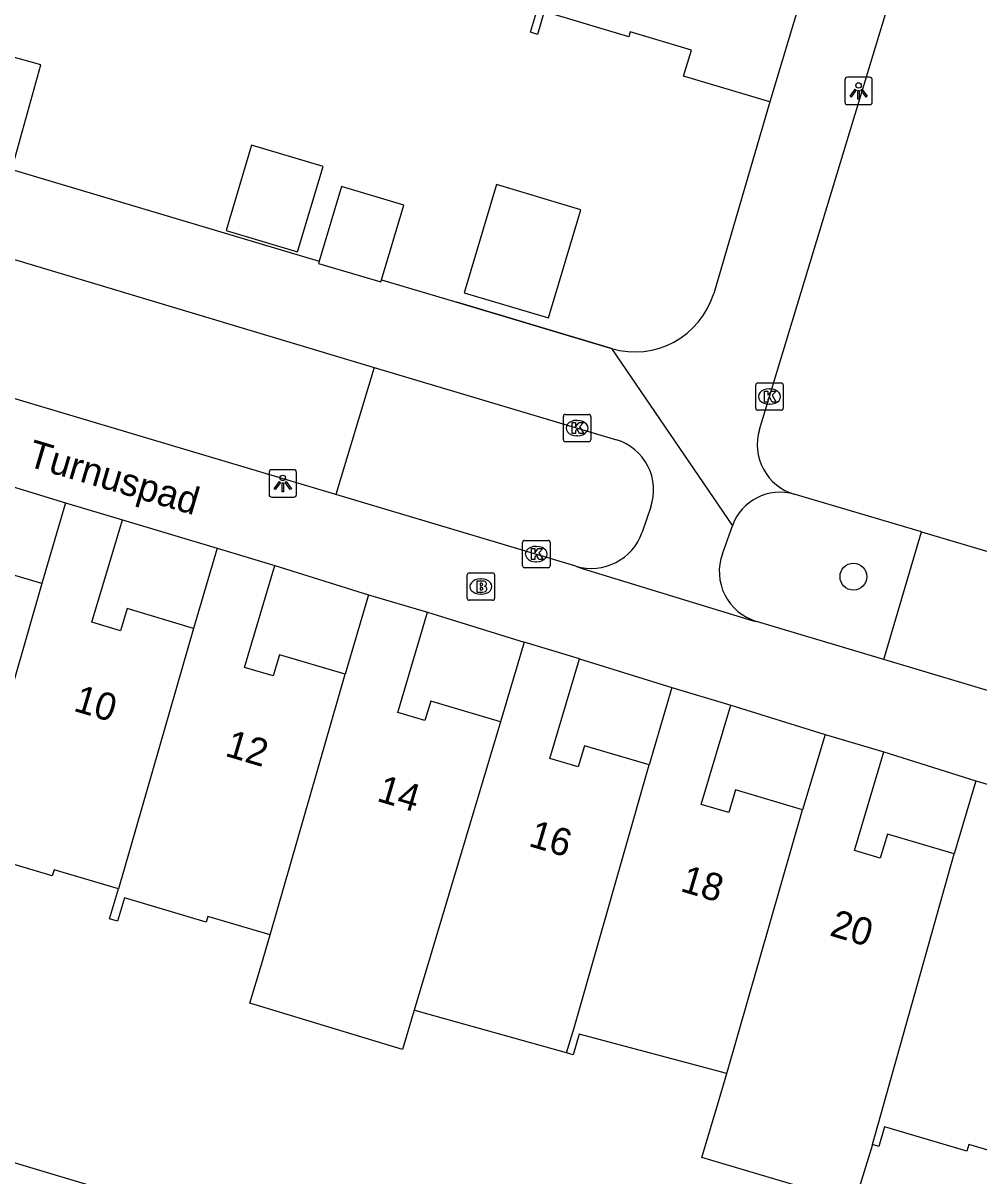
# Model space of a CAD drawing. Extents: x 162186 to 163152, y 385513 to 386513.
# Drawn here: x 162656.71 to 162691.57, y 386181.19 to 386223.24 of the extents above; entities that cross this region are included whole.
import ezdxf

# ---------------------------------------------------------------- set-up
doc = ezdxf.new("R2010")
doc.units = 0
for name, color, linetype in [('IMGEO_Boom', 7, 'Continuous'), ('IMGEO_Brandkraan', 7, 'Continuous'), ('IMGEO_Groenvoorziening', 7, 'Continuous'), ('IMGEO_Kolk', 7, 'Continuous'), ('IMGEO_Lichtpunt', 7, 'Continuous'), ('IMGEO_Muur', 7, 'Continuous'), ('IMGEO_Openbare_ruimte_label', 7, 'Continuous'), ('IMGEO_Pand', 7, 'Continuous'), ('IMGEO_Pand_nummerreeks', 7, 'Continuous'), ('IMGEO_Rijbaan_lokaal_open', 7, 'Continuous'), ('IMGEO_Voetpad_open', 7, 'Continuous')]:
    doc.layers.add(name, color=color, linetype=linetype)

msp = doc.modelspace()

# ---------------------------------------------------------------- linework, layer by layer
at = {"layer": 'IMGEO_Boom'}
msp.add_circle((162686.993, 386203.046), 0.489, dxfattribs=at)
at = {"layer": 'IMGEO_Brandkraan'}
for p, q in [((162672.907, 386202.259), (162672.907, 386203.111)), ((162672.982, 386203.185), (162673.834, 386203.185)), ((162673.395, 386202.965), (162673.42, 386202.965)), ((162673.908, 386203.111), (162673.908, 386202.259)), ((162673.834, 386202.185), (162672.982, 386202.185)), ((162673.418, 386202.405), (162673.393, 386202.405))]:
    msp.add_line(p, q, dxfattribs=at)
for points in [[(162672.907, 386202.259), (162672.907, 386203.111)], [(162672.982, 386203.185), (162673.834, 386203.185)], [(162673.908, 386203.111), (162673.908, 386202.259)], [(162673.255, 386202.885), (162673.255, 386202.485), (162673.468, 386202.485)], [(162673.486, 386202.885), (162673.255, 386202.885)], [(162673.434, 386202.804), (162673.38, 386202.804), (162673.38, 386202.728)], [(162673.38, 386202.728), (162673.433, 386202.728)], [(162673.442, 386202.652), (162673.38, 386202.652), (162673.38, 386202.571)], [(162673.38, 386202.571), (162673.442, 386202.571)], [(162673.834, 386202.185), (162672.982, 386202.185)]]:
    msp.add_lwpolyline(points, dxfattribs=at)
for centre, radius, start, end in [((162672.984, 386203.109), 0.0765, 91.552, 178.448), ((162672.984, 386203.109), 0.0765, 91.552, 178.448), ((162673.832, 386203.109), 0.0765, 1.552, 88.448), ((162673.832, 386203.109), 0.0765, 1.552, 88.448), ((162673.435, 386202.766), 0.0379, 267.8285, 90.9355), ((162673.443, 386202.611), 0.0404, 269.8759, 90.5077), ((162673.49, 386202.74), 0.145, 59.4692, 91.5367), ((162673.515, 386202.787), 0.0922, 285.5137, 58.1501), ((162673.52, 386202.595), 0.105, 301.3115, 78.989), ((162672.984, 386202.261), 0.0765, 181.552, 268.448), ((162672.984, 386202.261), 0.0765, 181.552, 268.448), ((162673.474, 386202.736), 0.251, 268.6676, 293.5347), ((162673.832, 386202.261), 0.0765, 271.552, 358.448), ((162673.832, 386202.261), 0.0765, 271.552, 358.448)]:
    msp.add_arc(centre, radius, start, end, dxfattribs=at)
for centre, major_axis, ratio, start_param, end_param in [((162673.394, 386202.685), (-0.387, 0.002), 0.722429, 4.712389, 7.853982), ((162673.419, 386202.685), (-0.39, 0.002), 0.717154, 1.570796, 4.712389)]:
    msp.add_ellipse(centre, major_axis=major_axis, ratio=ratio, start_param=start_param, end_param=end_param, dxfattribs=at)
at = {"layer": 'IMGEO_Groenvoorziening'}
for points in [[(162669.521, 386210.679), (162668.123, 386206.04)], [(162688.104, 386200.024), (162689.472, 386204.679)]]:
    msp.add_lwpolyline(points, dxfattribs=at)
at = {"layer": 'IMGEO_Kolk'}
for p, q in [((162683.507, 386210.114), (162684.359, 386210.114)), ((162683.432, 386209.188), (162683.432, 386210.04)), ((162683.92, 386209.894), (162683.945, 386209.894)), ((162684.433, 386210.04), (162684.433, 386209.188)), ((162683.943, 386209.334), (162683.918, 386209.334)), ((162676.414, 386208.039), (162676.414, 386208.891)), ((162676.489, 386208.965), (162677.341, 386208.965)), ((162677.415, 386208.891), (162677.415, 386208.039)), ((162684.359, 386209.114), (162683.507, 386209.114)), ((162676.902, 386208.745), (162676.927, 386208.745)), ((162676.925, 386208.185), (162676.9, 386208.185)), ((162677.341, 386207.965), (162676.489, 386207.965)), ((162674.928, 386203.444), (162674.928, 386204.296)), ((162675.003, 386204.37), (162675.855, 386204.37)), ((162675.929, 386204.296), (162675.929, 386203.444)), ((162675.416, 386204.15), (162675.441, 386204.15)), ((162675.855, 386203.37), (162675.003, 386203.37)), ((162675.439, 386203.59), (162675.414, 386203.59))]:
    msp.add_line(p, q, dxfattribs=at)
for points in [[(162683.507, 386210.114), (162684.359, 386210.114)], [(162683.432, 386209.188), (162683.432, 386210.04)], [(162683.753, 386209.814), (162683.876, 386209.814), (162683.876, 386209.663), (162684.006, 386209.814), (162684.17, 386209.814), (162684.024, 386209.663), (162684.177, 386209.414), (162684.025, 386209.414), (162683.94, 386209.578), (162683.876, 386209.511), (162683.876, 386209.414), (162683.753, 386209.414), (162683.753, 386209.814)], [(162684.433, 386210.04), (162684.433, 386209.188)], [(162676.414, 386208.039), (162676.414, 386208.891)], [(162676.489, 386208.965), (162677.341, 386208.965)], [(162677.415, 386208.891), (162677.415, 386208.039)], [(162684.359, 386209.114), (162683.507, 386209.114)], [(162676.735, 386208.665), (162676.858, 386208.665), (162676.858, 386208.514), (162676.988, 386208.665), (162677.152, 386208.665), (162677.006, 386208.514), (162677.159, 386208.265), (162677.007, 386208.265), (162676.922, 386208.429), (162676.858, 386208.362), (162676.858, 386208.265), (162676.735, 386208.265), (162676.735, 386208.665)], [(162677.341, 386207.965), (162676.489, 386207.965)], [(162674.928, 386203.444), (162674.928, 386204.296)], [(162675.003, 386204.37), (162675.855, 386204.37)], [(162675.929, 386204.296), (162675.929, 386203.444)], [(162675.249, 386204.07), (162675.372, 386204.07), (162675.372, 386203.919), (162675.502, 386204.07), (162675.666, 386204.07), (162675.52, 386203.919), (162675.673, 386203.67), (162675.521, 386203.67), (162675.436, 386203.834), (162675.372, 386203.767), (162675.372, 386203.67), (162675.249, 386203.67), (162675.249, 386204.07)], [(162675.855, 386203.37), (162675.003, 386203.37)]]:
    msp.add_lwpolyline(points, dxfattribs=at)
for centre, start, end in [((162683.509, 386210.038), 91.552, 178.448), ((162683.509, 386210.038), 91.552, 178.448), ((162684.357, 386210.038), 1.552, 88.448), ((162684.357, 386210.038), 1.552, 88.448), ((162676.491, 386208.889), 91.552, 178.448), ((162676.491, 386208.889), 91.552, 178.448), ((162677.339, 386208.889), 1.552, 88.448), ((162677.339, 386208.889), 1.552, 88.448), ((162683.509, 386209.19), 181.552, 268.448), ((162683.509, 386209.19), 181.552, 268.448), ((162684.357, 386209.19), 271.552, 358.448), ((162684.357, 386209.19), 271.552, 358.448), ((162676.491, 386208.041), 181.552, 268.448), ((162676.491, 386208.041), 181.552, 268.448), ((162677.339, 386208.041), 271.552, 358.448), ((162677.339, 386208.041), 271.552, 358.448), ((162675.005, 386204.294), 91.552, 178.448), ((162675.005, 386204.294), 91.552, 178.448), ((162675.853, 386204.294), 1.552, 88.448), ((162675.853, 386204.294), 1.552, 88.448), ((162675.005, 386203.446), 181.552, 268.448), ((162675.005, 386203.446), 181.552, 268.448), ((162675.853, 386203.446), 271.552, 358.448), ((162675.853, 386203.446), 271.552, 358.448)]:
    msp.add_arc(centre, 0.0765, start, end, dxfattribs=at)
for centre, major_axis, ratio, start_param, end_param in [((162683.919, 386209.614), (-0.387, 0.002), 0.722429, 4.712389, 7.853982), ((162683.944, 386209.614), (-0.39, 0.002), 0.717154, 1.570796, 4.712389), ((162676.901, 386208.465), (-0.387, 0.002), 0.722429, 4.712389, 7.853982), ((162676.926, 386208.465), (-0.39, 0.002), 0.717154, 1.570796, 4.712389), ((162675.415, 386203.87), (-0.387, 0.002), 0.722429, 4.712389, 7.853982), ((162675.44, 386203.87), (-0.39, 0.002), 0.717154, 1.570796, 4.712389)]:
    msp.add_ellipse(centre, major_axis=major_axis, ratio=ratio, start_param=start_param, end_param=end_param, dxfattribs=at)
at = {"layer": 'IMGEO_Lichtpunt'}
for p, q in [((162686.682, 386221.162), (162686.682, 386220.355)), ((162686.682, 386221.162), (162686.682, 386220.355)), ((162687.584, 386221.257), (162686.776, 386221.257)), ((162687.584, 386221.257), (162686.776, 386221.257)), ((162687.678, 386220.355), (162687.678, 386221.162)), ((162687.678, 386220.355), (162687.678, 386221.162)), ((162686.776, 386220.261), (162687.584, 386220.261)), ((162686.776, 386220.261), (162687.584, 386220.261)), ((162665.684, 386206.849), (162665.684, 386206.042)), ((162665.684, 386206.849), (162665.684, 386206.042)), ((162666.586, 386206.944), (162665.778, 386206.944)), ((162666.586, 386206.944), (162665.778, 386206.944)), ((162666.68, 386206.042), (162666.68, 386206.849)), ((162666.68, 386206.042), (162666.68, 386206.849)), ((162665.778, 386205.948), (162666.586, 386205.948)), ((162665.778, 386205.948), (162666.586, 386205.948))]:
    msp.add_line(p, q, dxfattribs=at)
for points in [[(162687.056, 386220.826), (162687.095, 386220.798), (162686.907, 386220.536), (162686.869, 386220.563), (162687.056, 386220.826)], [(162687.158, 386220.778), (162687.205, 386220.778), (162687.205, 386220.456), (162687.158, 386220.456), (162687.158, 386220.778)], [(162687.268, 386220.798), (162687.306, 386220.825), (162687.493, 386220.563), (162687.454, 386220.535), (162687.268, 386220.798)], [(162666.058, 386206.513), (162666.097, 386206.485), (162665.909, 386206.223), (162665.871, 386206.25), (162666.058, 386206.513)], [(162666.16, 386206.465), (162666.207, 386206.465), (162666.207, 386206.143), (162666.16, 386206.143), (162666.16, 386206.465)], [(162666.27, 386206.485), (162666.308, 386206.512), (162666.495, 386206.25), (162666.456, 386206.222), (162666.27, 386206.485)]]:
    msp.add_lwpolyline(points, dxfattribs=at)
for centre in [(162687.181, 386220.96), (162666.183, 386206.647)]:
    msp.add_circle(centre, 0.0994, dxfattribs=at)
for centre, start, end in [((162686.776, 386221.162), 90, 180), ((162686.776, 386221.162), 90, 180), ((162687.584, 386221.162), 0, 90), ((162687.584, 386221.162), 0, 90), ((162686.776, 386220.355), 180, 270), ((162686.776, 386220.355), 180, 270), ((162687.584, 386220.355), 270, 0), ((162687.584, 386220.355), 270, 360), ((162665.778, 386206.849), 90, 180), ((162665.778, 386206.849), 90, 180), ((162666.586, 386206.849), 0, 90), ((162666.586, 386206.849), 0, 90), ((162665.778, 386206.042), 180, 270), ((162665.778, 386206.042), 180, 270), ((162666.586, 386206.042), 270, 0), ((162666.586, 386206.042), 270, 360)]:
    msp.add_arc(centre, 0.0946, start, end, dxfattribs=at)
at = {"layer": 'IMGEO_Muur'}
for points in [[(162683.948, 386220.358), (162681.897, 386213.378)], [(162678.17, 386211.368), (162672.525, 386213.051)]]:
    msp.add_lwpolyline(points, dxfattribs=at)
msp.add_arc((162679.025, 386214.243), 2.999, 253.4323, 343.2444, dxfattribs=at)
at = {"layer": 'IMGEO_Pand'}
for points in [[(162686.565, 386229.103), (162683.948, 386220.358)], [(162683.948, 386220.358), (162680.8, 386221.3), (162681.084, 386222.247), (162678.853, 386222.915), (162678.799, 386222.737), (162675.72, 386223.659), (162675.469, 386222.822), (162675.215, 386222.898), (162675.507, 386223.871)], [(162656.387, 386218.216), (162657.362, 386221.709), (162654.172, 386222.599), (162653.198, 386219.106), (162656.387, 386218.216)], [(162666.725, 386214.895), (162667.657, 386218.007), (162665.047, 386218.788), (162664.116, 386215.676), (162666.725, 386214.895)], [(162669.78, 386213.87), (162670.595, 386216.59), (162668.325, 386217.27), (162667.509, 386214.547)], [(162675.869, 386212.483), (162677.049, 386216.423), (162673.978, 386217.342), (162672.798, 386213.402), (162675.869, 386212.483)], [(162667.509, 386214.547), (162667.487, 386214.472), (162669.757, 386213.792), (162669.78, 386213.87)], [(162657.393, 386202.799), (162654.964, 386203.52), (162654.722, 386202.706), (162653.64, 386203.027), (162654.763, 386206.811)], [(162658.264, 386205.736), (162657.393, 386202.799)], [(162658.264, 386205.736), (162660.333, 386205.122)], [(162662.925, 386201.161), (162660.505, 386201.88), (162660.266, 386201.073), (162659.224, 386201.382), (162660.333, 386205.122)], [(162663.794, 386204.082), (162662.925, 386201.161)], [(162663.794, 386204.082), (162665.894, 386203.459)], [(162668.454, 386199.488), (162666.058, 386200.198), (162665.828, 386199.424), (162664.788, 386199.732), (162665.894, 386203.459)], [(162657.393, 386202.799), (162654.673, 386193.336)], [(162669.313, 386202.384), (162668.454, 386199.488)], [(162669.313, 386202.384), (162671.463, 386201.746)], [(162674.12, 386197.756), (162671.577, 386198.51), (162671.367, 386197.801), (162670.38, 386198.094), (162671.463, 386201.746)], [(162662.925, 386201.161), (162660.191, 386191.658)], [(162674.98, 386200.654), (162674.12, 386197.756)], [(162677.007, 386200.053), (162674.98, 386200.654)], [(162679.539, 386196.182), (162677.18, 386196.882), (162676.95, 386196.108), (162675.926, 386196.412), (162677.007, 386200.053)], [(162665.724, 386189.984), (162668.454, 386199.488)], [(162680.375, 386199.002), (162679.539, 386196.182)], [(162680.375, 386199.002), (162682.52, 386198.365)], [(162685.141, 386194.547), (162682.695, 386195.273), (162682.448, 386194.44), (162681.444, 386194.738), (162682.52, 386198.365)], [(162674.12, 386197.756), (162670.97, 386187.241)], [(162685.957, 386197.294), (162685.141, 386194.547)], [(162685.957, 386197.294), (162688.098, 386196.659)], [(162690.669, 386192.933), (162688.232, 386193.656), (162687.972, 386192.78), (162687.03, 386193.059), (162688.098, 386196.659)], [(162676.533, 386185.682), (162676.804, 386186.593), (162679.539, 386196.182)], [(162691.463, 386195.604), (162690.669, 386192.933)], [(162691.463, 386195.604), (162693.622, 386194.963)], [(162682.375, 386184.93), (162685.141, 386194.547)], [(162660.191, 386191.658), (162657.841, 386192.355), (162657.775, 386192.133), (162654.866, 386192.996), (162654.628, 386192.159), (162654.409, 386192.224), (162654.673, 386193.336)], [(162687.686, 386182.336), (162690.669, 386192.933)], [(162665.724, 386189.984), (162663.455, 386190.658), (162663.394, 386190.452), (162660.41, 386191.337), (162660.158, 386190.488), (162659.869, 386190.574), (162660.191, 386191.658)], [(162670.97, 386187.241), (162670.543, 386185.797), (162664.983, 386187.492), (162665.403, 386188.904), (162665.724, 386189.984)], [(162676.533, 386185.682), (162671.213, 386187.169), (162670.97, 386187.241)], [(162682.375, 386184.93), (162676.996, 386186.36), (162676.773, 386185.611), (162676.533, 386185.682)], [(162687.686, 386182.336), (162687.034, 386180.211), (162681.466, 386181.862), (162682.092, 386183.975), (162682.375, 386184.93)], [(162693.464, 386181.665), (162691.204, 386182.336), (162691.132, 386182.093), (162688.131, 386182.984), (162687.918, 386182.267), (162687.686, 386182.336)]]:
    msp.add_lwpolyline(points, dxfattribs=at)
at = {"layer": 'IMGEO_Rijbaan_lokaal_open'}
for points in [[(162683.566, 386208.408), (162690.136, 386230.062)], [(162689.472, 386204.679), (162684.836, 386206.051)], [(162689.472, 386204.679), (162701.811, 386201.027), (162701.908, 386200.996)]]:
    msp.add_lwpolyline(points, dxfattribs=at)
msp.add_arc((162685.373, 386207.861), 1.888, 163.1468, 253.4866, dxfattribs=at)
at = {"layer": 'IMGEO_Voetpad_open'}
for points in [[(162683.948, 386220.358), (162681.897, 386213.378)], [(162650.593, 386219.592), (162667.509, 386214.547)], [(162643.529, 386218.419), (162651.203, 386216.166), (162669.521, 386210.679)], [(162668.123, 386206.04), (162651.146, 386211.101), (162642.14, 386213.753)], [(162669.78, 386213.87), (162672.525, 386213.051), (162678.17, 386211.368)], [(162678.17, 386211.368), (162682.581, 386204.898)], [(162669.521, 386210.679), (162678.347, 386208.035)], [(162654.763, 386206.811), (162658.264, 386205.736)], [(162676.868, 386203.433), (162668.123, 386206.04)], [(162679.604, 386205.587), (162679.292, 386204.673)], [(162660.333, 386205.122), (162663.794, 386204.082)], [(162682.213, 386203.881), (162682.581, 386204.898)], [(162665.894, 386203.459), (162669.313, 386202.384)], [(162676.868, 386203.433), (162677.098, 386203.344), (162683.339, 386201.439), (162683.454, 386201.416)], [(162671.463, 386201.746), (162674.98, 386200.654)], [(162688.104, 386200.024), (162683.454, 386201.416)], [(162677.007, 386200.053), (162680.375, 386199.002)], [(162700.454, 386196.325), (162688.104, 386200.024)], [(162682.52, 386198.365), (162685.957, 386197.294)], [(162688.098, 386196.659), (162691.463, 386195.604)], [(162699.756, 386171.624), (162699.657, 386171.381), (162699.537, 386171.147), (162699.396, 386170.925), (162699.236, 386170.717), (162699.058, 386170.524), (162698.864, 386170.347), (162698.654, 386170.188), (162698.431, 386170.049), (162698.197, 386169.931), (162697.953, 386169.833), (162697.701, 386169.758), (162697.444, 386169.706), (162697.183, 386169.677), (162696.92, 386169.671), (162696.658, 386169.689), (162696.399, 386169.73), (162696.144, 386169.794), (162666.99, 386178.501), (162649.189, 386183.818), (162649.012, 386183.871)]]:
    msp.add_lwpolyline(points, dxfattribs=at)
for centre, radius, start, end in [((162679.025, 386214.243), 2.999, 253.4323, 343.2444), ((162677.794, 386206.204), 1.913, 341.1762, 73.183), ((162684.318, 386204.282), 1.843, 73.6911, 160.471), ((162677.44, 386205.304), 1.956, 252.9905, 341.1937), ((162683.999, 386203.235), 1.899, 160.133, 253.3127)]:
    msp.add_arc(centre, radius, start, end, dxfattribs=at)

# ---------------------------------------------------------------- texts
at = {"layer": 'IMGEO_Openbare_ruimte_label'}
msp.add_text('Turnuspad', height=1, rotation=343.5587, dxfattribs=at).set_placement((162656.818, 386207.094))
at = {"layer": 'IMGEO_Pand_nummerreeks'}
for s, rotation, p in [('10', 343.4539, (162658.511, 386198.163)), ('12', 343.4539, (162664.038, 386196.521)), ('14', 343.4539, (162669.574, 386194.876)), ('16', 343.453, (162675.108, 386193.232)), ('18', 343.4539, (162680.642, 386191.588)), ('20', 343.4539, (162686.088, 386189.97))]:
    msp.add_text(s, height=1, rotation=rotation, dxfattribs=at).set_placement(p)

doc.saveas('drawing.dxf')
